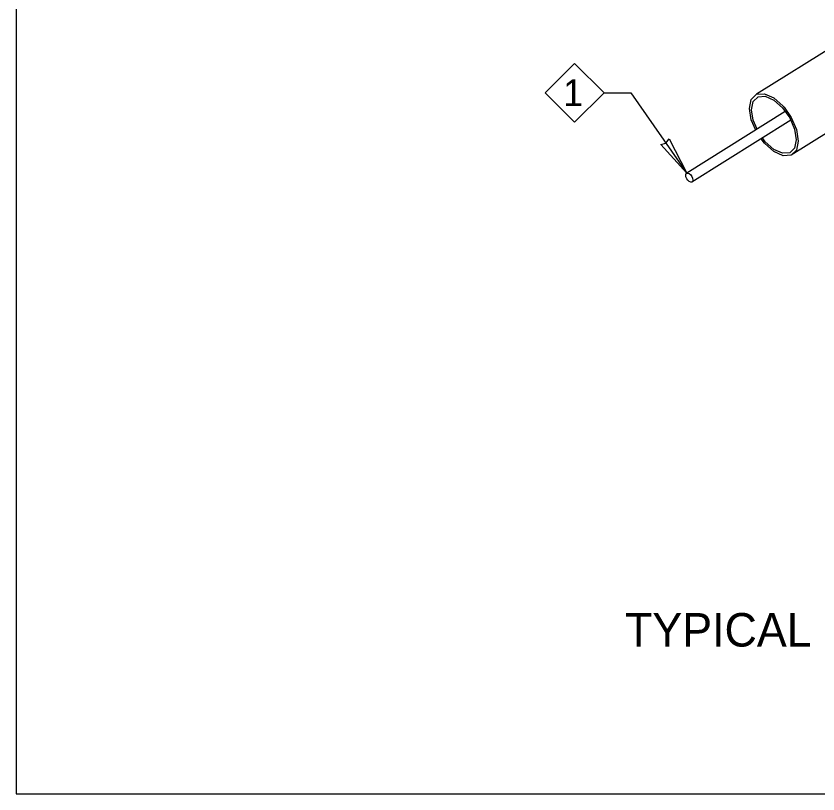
# Model space of a CAD drawing. Extents: x 99862 to 103151, y 100000 to 105076.
# Drawn here: x 99862 to 100340.9, y 99999.5 to 100464 of the extents above; entities that cross this region are included whole.
import ezdxf

# ---------------------------------------------------------------- set-up
doc = ezdxf.new("R2010")
doc.units = 0
for name, color, linetype in [('Level 1', 7, 'Continuous'), ('Level 15', 7, 'Continuous'), ('Level 20', 7, 'Continuous'), ('Level 60', 7, 'Continuous')]:
    doc.layers.add(name, color=color, linetype=linetype)

msp = doc.modelspace()

# ---------------------------------------------------------------- linework, layer by layer
at = {"layer": 'Level 1'}
msp.add_line((100444.77, 100505.11), (100304.29, 100417.32), dxfattribs=at)
msp.add_lwpolyline([(99862, 99999.5), (103151, 99999.5), (103151, 102075.5), (99862, 102075.5)], close=True, dxfattribs=at)
for points in [[(100493.31, 100486.09), (100324.91, 100380.85), (100320.18, 100380.56), (100314.6, 100383.09), (100309.02, 100388.05), (100307.09, 100390.76)], [(100303.75, 100395.94), (100301.13, 100402.01), (100300.02, 100408.87), (100301.13, 100414.25), (100304.29, 100417.32)], [(100304.29, 100417.32), (100309.02, 100417.61), (100314.6, 100415.08), (100320.18, 100410.12), (100320.66, 100409.56), (100324.91, 100403.48), (100328.07, 100396.16), (100329.18, 100389.3), (100328.07, 100383.92), (100324.91, 100380.85)], [(100305.13, 100415.84), (100309.47, 100416.11), (100314.6, 100413.78), (100319.72, 100409.22), (100324.07, 100403.12), (100326.97, 100396.4), (100327.99, 100390.09), (100326.97, 100385.15), (100324.07, 100382.33), (100324.07, 100382.33)], [(100304.53, 100396.43), (100302.22, 100401.77), (100301.2, 100408.08), (100302.22, 100413.02), (100305.13, 100415.84)], [(100321.35, 100406.94), (100262.57, 100370.21), (100263.27, 100370.26), (100264.09, 100369.88), (100264.92, 100369.15), (100265.61, 100368.17), (100266.08, 100367.09), (100266.24, 100366.08), (100266.08, 100365.29), (100265.61, 100364.84)], [(100324.67, 100401.74), (100265.61, 100364.84), (100264.92, 100364.79), (100264.09, 100365.17), (100263.27, 100365.9), (100262.57, 100366.88), (100262.11, 100367.96), (100261.94, 100368.97), (100262.11, 100369.76), (100262.57, 100370.21)], [(100324.07, 100382.33), (100319.72, 100382.06), (100314.6, 100384.39), (100309.47, 100388.95), (100307.85, 100391.23)]]:
    msp.add_lwpolyline(points, dxfattribs=at)
at = {"layer": 'Level 15'}
for p, q in [((100213.16, 100418.18), (100229.16, 100418.18)), ((100229.16, 100418.18), (100262.57, 100370.21))]:
    msp.add_line(p, q, dxfattribs=at)
msp.add_lwpolyline([(100262.57, 100370.21), (100247.08, 100387.24), (100250.13, 100388.08), (100251.97, 100390.65)], close=True, dxfattribs=at)
at = {"layer": 'Level 20'}
msp.add_lwpolyline([(100195.61, 100435.73), (100213.16, 100418.18), (100195.61, 100400.63), (100178.05, 100418.18)], close=True, dxfattribs=at)
at = {"layer": 'Level 60'}
msp.add_line((99862, 99999.5), (99862, 99999.5), dxfattribs=at)

# ---------------------------------------------------------------- texts
at = {"layer": 'Level 20'}
for s, height, p in [('1', 16, (100188.74, 100410.18)), ('TYPICAL GROUNDING AND BONDING', 20, (100225.68, 100087.51))]:
    msp.add_text(s, height=height, dxfattribs=at).set_placement(p)

doc.saveas('drawing.dxf')
